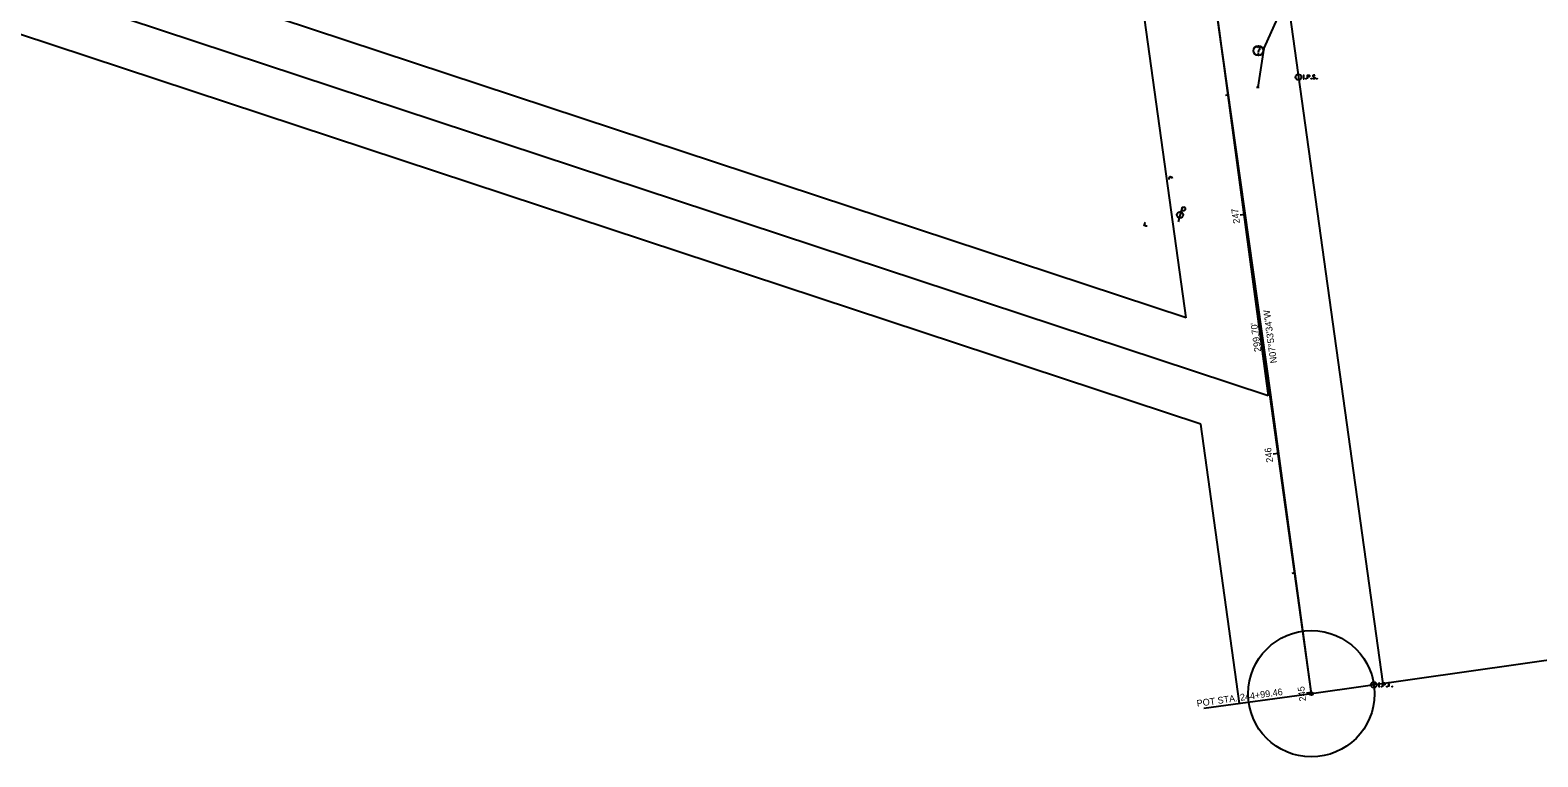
# Model space of a CAD drawing. Extents: x -3537 to 31, y -1364 to 432.
# Drawn here: x -3127 to -2689.7, y -1363.6 to -1152.8 of the extents above; entities that cross this region are included whole.
import ezdxf

# ---------------------------------------------------------------- set-up
doc = ezdxf.new("R2010")
doc.units = 0
for name, color, linetype in [('Default', 7, 'Continuous'), ('DT_X_Contour_Minor', 7, 'Continuous'), ('DT_X_Terrain_Ground_Line', 7, 'Continuous'), ('DT_X_Triangles', 7, 'Continuous'), ('UT_X_Electric_Cells', 7, 'Continuous')]:
    doc.layers.add(name, color=color, linetype=linetype)

msp = doc.modelspace()

# ---------------------------------------------------------------- linework, layer by layer
at = {"layer": 'Default'}
for p, q in [((-2789.55, -1251.68), (-3125.97, -1140.56)), ((-2767.09, -1258.58), (-2784.18, -1137.49)), ((-2784.18, -1137.5), (-2767.89, -1258.83)), ((-2770.74, -1159.25), (-2770.74, -1158.91)), ((-2769.54, -1157.98), (-2768.84, -1157.98)), ((-2769.19, -1157.63), (-2769.19, -1158.33)), ((-2769.19, -1157.98), (-2769.19, -1157.98)), ((-2779.46, -1171.58), (-2780.29, -1171.69)), ((-2771.25, -1169.29), (-2770.55, -1169.29)), ((-2770.9, -1168.94), (-2770.9, -1169.64)), ((-2770.9, -1169.29), (-2770.9, -1169.29)), ((-2792.89, -1204.15), (-2794.02, -1208.35)), ((-2793.13, -1205.04), (-2792.3, -1205.04)), ((-2792.89, -1204.15), (-2792.3, -1204.15)), ((-2774.65, -1206.25), (-2776.04, -1206.44)), ((-2769.84, -1240.91), (-2770.68, -1241.03)), ((-2767.89, -1258.83), (-2789.55, -1251.68)), ((-2755.37, -1345.29), (-2767.09, -1258.58)), ((-2765.04, -1275.58), (-2766.42, -1275.77)), ((-2487.36, -1307.46), (-2755.37, -1345.29)), ((-2760.23, -1310.25), (-2761.06, -1310.37)), ((-2755.37, -1345.29), (-2786.58, -1349.62)), ((-2755.43, -1344.92), (-2756.81, -1345.11)), ((-2737.23, -1342.65), (-2737.23, -1343.27))]:
    msp.add_line(p, q, dxfattribs=at)
for points in [[(-2735.81, -1342.17), (-2735.57, -1342.17)], [(-2735.69, -1343.29), (-2735.69, -1342.17)], [(-2734.59, -1343.29), (-2734.59, -1342.17), (-2734.22, -1342.17), (-2734.18, -1342.18), (-2734.13, -1342.2), (-2734.11, -1342.22), (-2734.08, -1342.23), (-2734.05, -1342.28), (-2734.03, -1342.32), (-2734.02, -1342.39), (-2734.02, -1342.5), (-2734.02, -1342.53), (-2734.04, -1342.59), (-2734.07, -1342.65), (-2734.1, -1342.68), (-2734.12, -1342.69), (-2734.16, -1342.71), (-2734.22, -1342.72), (-2734.59, -1342.72)], [(-2732.49, -1342.17), (-2733.02, -1342.17), (-2733.02, -1343.29)], [(-2735.81, -1343.29), (-2735.57, -1343.29)], [(-2735.02, -1343.14), (-2734.98, -1343.14), (-2734.96, -1343.16), (-2734.93, -1343.2), (-2734.93, -1343.24), (-2734.96, -1343.28), (-2734.98, -1343.29), (-2735.02, -1343.29), (-2735.04, -1343.28), (-2735.06, -1343.24), (-2735.06, -1343.2), (-2735.04, -1343.16), (-2735.02, -1343.14)], [(-2733.44, -1343.14), (-2733.41, -1343.14), (-2733.38, -1343.16), (-2733.36, -1343.2), (-2733.36, -1343.24), (-2733.38, -1343.28), (-2733.41, -1343.29), (-2733.44, -1343.29), (-2733.47, -1343.28), (-2733.49, -1343.24), (-2733.49, -1343.2), (-2733.47, -1343.16), (-2733.44, -1343.14)], [(-2733.02, -1342.72), (-2732.64, -1342.72)], [(-2731.94, -1343.14), (-2731.9, -1343.14), (-2731.88, -1343.16), (-2731.85, -1343.2), (-2731.85, -1343.24), (-2731.88, -1343.28), (-2731.9, -1343.29), (-2731.94, -1343.29), (-2731.96, -1343.28), (-2731.99, -1343.24), (-2731.99, -1343.2), (-2731.96, -1343.16), (-2731.94, -1343.14)]]:
    msp.add_lwpolyline(points, dxfattribs=at)
for centre, radius in [((-2770.74, -1158.72), 1.4), ((-2770.74, -1159.71), 0.119), ((-2796.32, -1195.4), 0.14), ((-2793.49, -1206.39), 0.91), ((-2803.74, -1209.32), 0.14), ((-2755.37, -1345.29), 18.32), ((-2737.23, -1342.73), 0.84), ((-2737.23, -1342.28), 0.112), ((-2755.37, -1345.29), 0.42)]:
    msp.add_circle(centre, radius, dxfattribs=at)
for centre, radius, start, end in [((-2770.78, -1158.15), 0.528, 88.324, 152.5385), ((-2770.75, -1158.1), 0.481, 291.9329, 92.4584), ((-2770.33, -1158.88), 0.411, 125.4618, 184.0829), ((-2796.18, -1195.94), 0.56, 14.4463, 194.4463), ((-2792.29, -1204.59), 0.446, 268.8767, 91.1233), ((-2803.26, -1209.02), 0.56, 121.9256, 301.9256)]:
    msp.add_arc(centre, radius, start, end, dxfattribs=at)
at = {"layer": 'DT_X_Contour_Minor'}
msp.add_lwpolyline([(-2738.59, -1135.54), (-2750.84, -1139.77), (-2759.31, -1144.23), (-2765.3, -1149.37), (-2769.19, -1157.98), (-2770.9, -1169.29)], dxfattribs=at)
at = {"layer": 'DT_X_Terrain_Ground_Line'}
msp.add_line((-2755.37, -1345.29), (-2784.18, -1137.49), dxfattribs=at)
at = {"layer": 'DT_X_Triangles'}
for p, q in [((-2791.69, -1236.22), (-3121.58, -1127.26)), ((-2791.69, -1236.22), (-2805, -1140.29)), ((-2734.57, -1342.41), (-2761.58, -1147.6)), ((-2787.41, -1267.13), (-3130.36, -1153.85)), ((-2776.17, -1348.18), (-2787.41, -1267.13))]:
    msp.add_line(p, q, dxfattribs=at)
at = {"layer": 'UT_X_Electric_Cells'}
for points in [[(-2757.71, -1165.79), (-2757.46, -1165.79)], [(-2757.71, -1166.91), (-2757.46, -1166.91)], [(-2757.58, -1166.91), (-2757.58, -1165.79)], [(-2756.91, -1166.76), (-2756.87, -1166.76), (-2756.85, -1166.78), (-2756.83, -1166.82), (-2756.83, -1166.86), (-2756.85, -1166.9), (-2756.87, -1166.91), (-2756.91, -1166.91), (-2756.93, -1166.9), (-2756.96, -1166.86), (-2756.96, -1166.82), (-2756.93, -1166.78), (-2756.91, -1166.76)], [(-2756.49, -1166.91), (-2756.49, -1165.79), (-2756.12, -1165.79), (-2756.08, -1165.8), (-2756.02, -1165.82), (-2756, -1165.84), (-2755.98, -1165.86), (-2755.95, -1165.9), (-2755.92, -1165.94), (-2755.91, -1166.01), (-2755.91, -1166.12), (-2755.92, -1166.16), (-2755.93, -1166.21), (-2755.96, -1166.27), (-2755.99, -1166.3), (-2756.02, -1166.31), (-2756.06, -1166.33), (-2756.12, -1166.34), (-2756.49, -1166.34)], [(-2755.34, -1166.76), (-2755.3, -1166.76), (-2755.28, -1166.78), (-2755.25, -1166.82), (-2755.25, -1166.86), (-2755.28, -1166.9), (-2755.3, -1166.91), (-2755.34, -1166.91), (-2755.36, -1166.9), (-2755.38, -1166.86), (-2755.38, -1166.82), (-2755.36, -1166.78), (-2755.34, -1166.76)], [(-2754.38, -1165.87), (-2754.4, -1165.86), (-2754.42, -1165.84), (-2754.49, -1165.81), (-2754.57, -1165.79), (-2754.64, -1165.79), (-2754.66, -1165.79), (-2754.76, -1165.82), (-2754.84, -1165.87), (-2754.9, -1165.94), (-2754.91, -1166.01), (-2754.91, -1166.07), (-2754.9, -1166.14), (-2754.84, -1166.2), (-2754.41, -1166.46), (-2754.37, -1166.5), (-2754.36, -1166.54), (-2754.34, -1166.59), (-2754.34, -1166.64), (-2754.35, -1166.69), (-2754.36, -1166.73), (-2754.37, -1166.77), (-2754.39, -1166.81), (-2754.4, -1166.83), (-2754.43, -1166.86), (-2754.45, -1166.88), (-2754.48, -1166.9), (-2754.5, -1166.91), (-2754.57, -1166.91), (-2754.68, -1166.91), (-2754.75, -1166.9), (-2754.85, -1166.83), (-2754.91, -1166.78)], [(-2753.81, -1166.76), (-2753.77, -1166.76), (-2753.75, -1166.78), (-2753.72, -1166.82), (-2753.72, -1166.86), (-2753.75, -1166.9), (-2753.77, -1166.91), (-2753.81, -1166.91), (-2753.83, -1166.9), (-2753.86, -1166.86), (-2753.86, -1166.82), (-2753.83, -1166.78), (-2753.81, -1166.76)]]:
    msp.add_lwpolyline(points, dxfattribs=at)
msp.add_circle((-2759.12, -1166.36), 0.84, dxfattribs=at)

# ---------------------------------------------------------------- texts
at = {"layer": 'Default'}
for s, rotation, p in [('247', 97.8928, (-2776.07, -1208.73)), ('N07°53\'34"W', 97.8928, (-2765.29, -1249.27)), ("299.70'", 97.8928, (-2769.92, -1245.96)), ('246', 97.8928, (-2766.46, -1278.08)), ('POT STA. 244+99.46', 7.8928, (-2788.48, -1349.1)), ('245', 97.8928, (-2756.85, -1347.38))]:
    msp.add_text(s, height=1.96, rotation=rotation, dxfattribs=at).set_placement(p)

doc.saveas('drawing.dxf')
